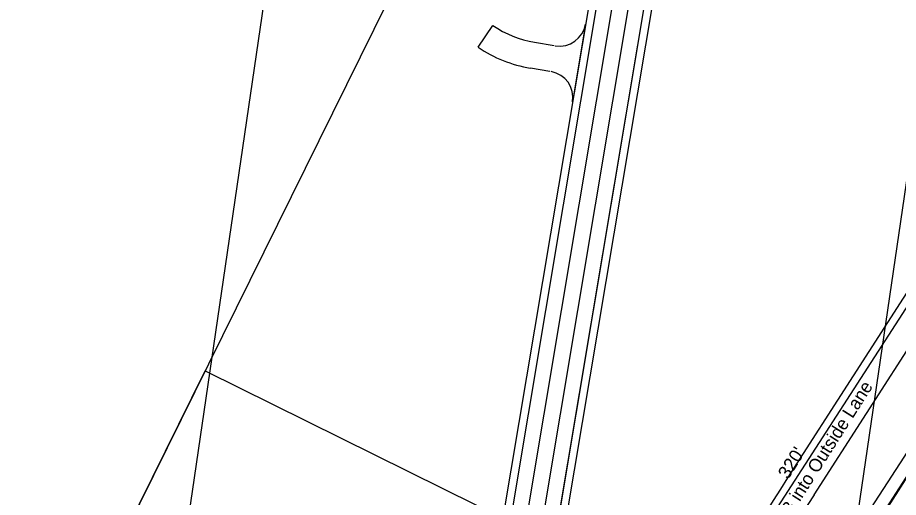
# Model space of a CAD drawing. Extents: x 14104283 to 14128447, y 8633203 to 8671666.
# Drawn here: x 14118644 to 14119316, y 8669162 to 8669528 of the extents above; entities that cross this region are included whole.
import ezdxf

# ---------------------------------------------------------------- set-up
doc = ezdxf.new("R2010")
doc.units = 0
for name, color, linetype in [('dsnNonPlotable', 7, 'Continuous'), ('dsnPaintExistingEdgeLineRightWhite', 7, 'Continuous'), ('dsnPaintExistingNoPassingYellow', 7, 'Continuous'), ('dsnShadingPaved', 7, 'Continuous'), ('dsnStdLabel', 7, 'Continuous'), ('dsnStgShadingPrevPav', 7, 'Continuous'), ('dsnStgShadingPropPav', 7, 'Continuous')]:
    doc.layers.add(name, color=color, linetype=linetype)

msp = doc.modelspace()

# ---------------------------------------------------------------- linework, layer by layer
at = {"layer": 'dsnNonPlotable'}
for points in [[(14118774.15, 8669147.84), (14119001.66, 8670698.74), (14119501.31, 8670625.45), (14119273.81, 8669074.54)], [(14118631.64, 8668945.1), (14119326.37, 8670350.23), (14120231.75, 8669902.59), (14119537.02, 8668497.46)], [(14118092.03, 8667853.71), (14118786.76, 8669258.84), (14119692.14, 8668811.2), (14118997.41, 8667406.07)]]:
    msp.add_lwpolyline(points, close=True, dxfattribs=at)
at = {"layer": 'dsnPaintExistingEdgeLineRightWhite'}
msp.add_line((14119184.51, 8670128.17), (14119019.22, 8669141.32), dxfattribs=at)
msp.add_line((14119184.51, 8670128.17), (14119019.22, 8669141.32), dxfattribs=at)
for points in [[(14119029.87, 8669002.67), (14119054.72, 8669135.38), (14119224.18, 8670147.05)], [(14119029.87, 8669002.67), (14119054.72, 8669135.38), (14119224.18, 8670147.05)], [(14119412.15, 8669317.07), (14119387.62, 8669279), (14119355.61, 8669229.26), (14119328.75, 8669187.71), (14119296.91, 8669137.95), (14119267.45, 8669092.09), (14119237.9, 8669046.84), (14119206.91, 8668999.35), (14119178.97, 8668956.72), (14119155.37, 8668919.99)]]:
    msp.add_lwpolyline(points, dxfattribs=at)
at = {"layer": 'dsnPaintExistingNoPassingYellow'}
for p, q in [((14119031.05, 8669139.34), (14119200.51, 8670151.01)), ((14119212.34, 8670149.03), (14119042.89, 8669137.36))]:
    msp.add_line(p, q, dxfattribs=at)
at = {"layer": 'dsnShadingPaved'}
for p, q in [((14119188.66, 8670152.92), (14119019.21, 8669141.25)), ((14119031.04, 8669139.27), (14119200.49, 8670150.94)), ((14119031.05, 8669139.34), (14119200.51, 8670151.01)), ((14119212.34, 8670149.03), (14119042.89, 8669137.36)), ((14119212.34, 8670149.03), (14119042.89, 8669137.36)), ((14119054.72, 8669135.38), (14119224.18, 8670147.05)), ((14119155.5, 8668919.9), (14119497.22, 8669449.29))]:
    msp.add_line(p, q, dxfattribs=at)
at = {"layer": 'dsnStdLabel'}
msp.add_line((14119150.89, 8669041.84), (14119324.44, 8669310.7), dxfattribs=at)
at = {"layer": 'dsnStgShadingPrevPav'}
for p, q in [((14119060.64, 8669134.39), (14119230.09, 8670146.06)), ((14119151.79, 8669969.11), (14119013.3, 8669142.32)), ((14118995.18, 8669505.9), (14119006.45, 8669522.42)), ((14119077.13, 8669523.38), (14119067.22, 8669464.21)), ((14119038.32, 8669509.6), (14119053.13, 8669507.12)), ((14119049.83, 8669487.4), (14119035.02, 8669489.88))]:
    msp.add_line(p, q, dxfattribs=at)
msp.add_lwpolyline([(14119144.14, 8668920.3), (14119170.94, 8668961.91), (14119198.95, 8669005.04), (14119229.55, 8669052.67), (14119259.7, 8669099.16), (14119288.84, 8669144.53), (14119320.43, 8669193.09), (14119347.13, 8669234.7), (14119379.16, 8669285.01), (14119403.27, 8669322.21)], dxfattribs=at)
for centre, radius, start, end in [((14119051.53, 8669588.5), 80, 235.69513, 260.49147), ((14119057.4, 8669526.69), 20, 260.49147, 350.49147), ((14119051.53, 8669588.5), 100, 235.69513, 260.49147), ((14119047.49, 8669467.51), 20, 350.49147, 80.49147)]:
    msp.add_arc(centre, radius, start, end, dxfattribs=at)
at = {"layer": 'dsnStgShadingPropPav'}
for p, q in [((14119434.72, 8669493.24), (14119231.48, 8669177.36)), ((14119251.66, 8669164.37), (14119454.9, 8669480.25))]:
    msp.add_line(p, q, dxfattribs=at)
for radius, end in [(1512, 159.62671), (1488, 158.15787)]:
    msp.add_arc((14120503.02, 8668359.24), radius, 147.24256, end, dxfattribs=at)

# ---------------------------------------------------------------- texts
at = {"layer": 'dsnStdLabel'}
for s, p in [('Merge SB into Outside Lane', (14119206.91, 8669105.32)), ("320'", (14119231.83, 8669175.69))]:
    msp.add_text(s, height=10, rotation=57.60023, dxfattribs=at).set_placement(p)

doc.saveas('drawing.dxf')
